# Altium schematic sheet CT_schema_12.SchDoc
size 385 x 278 mm
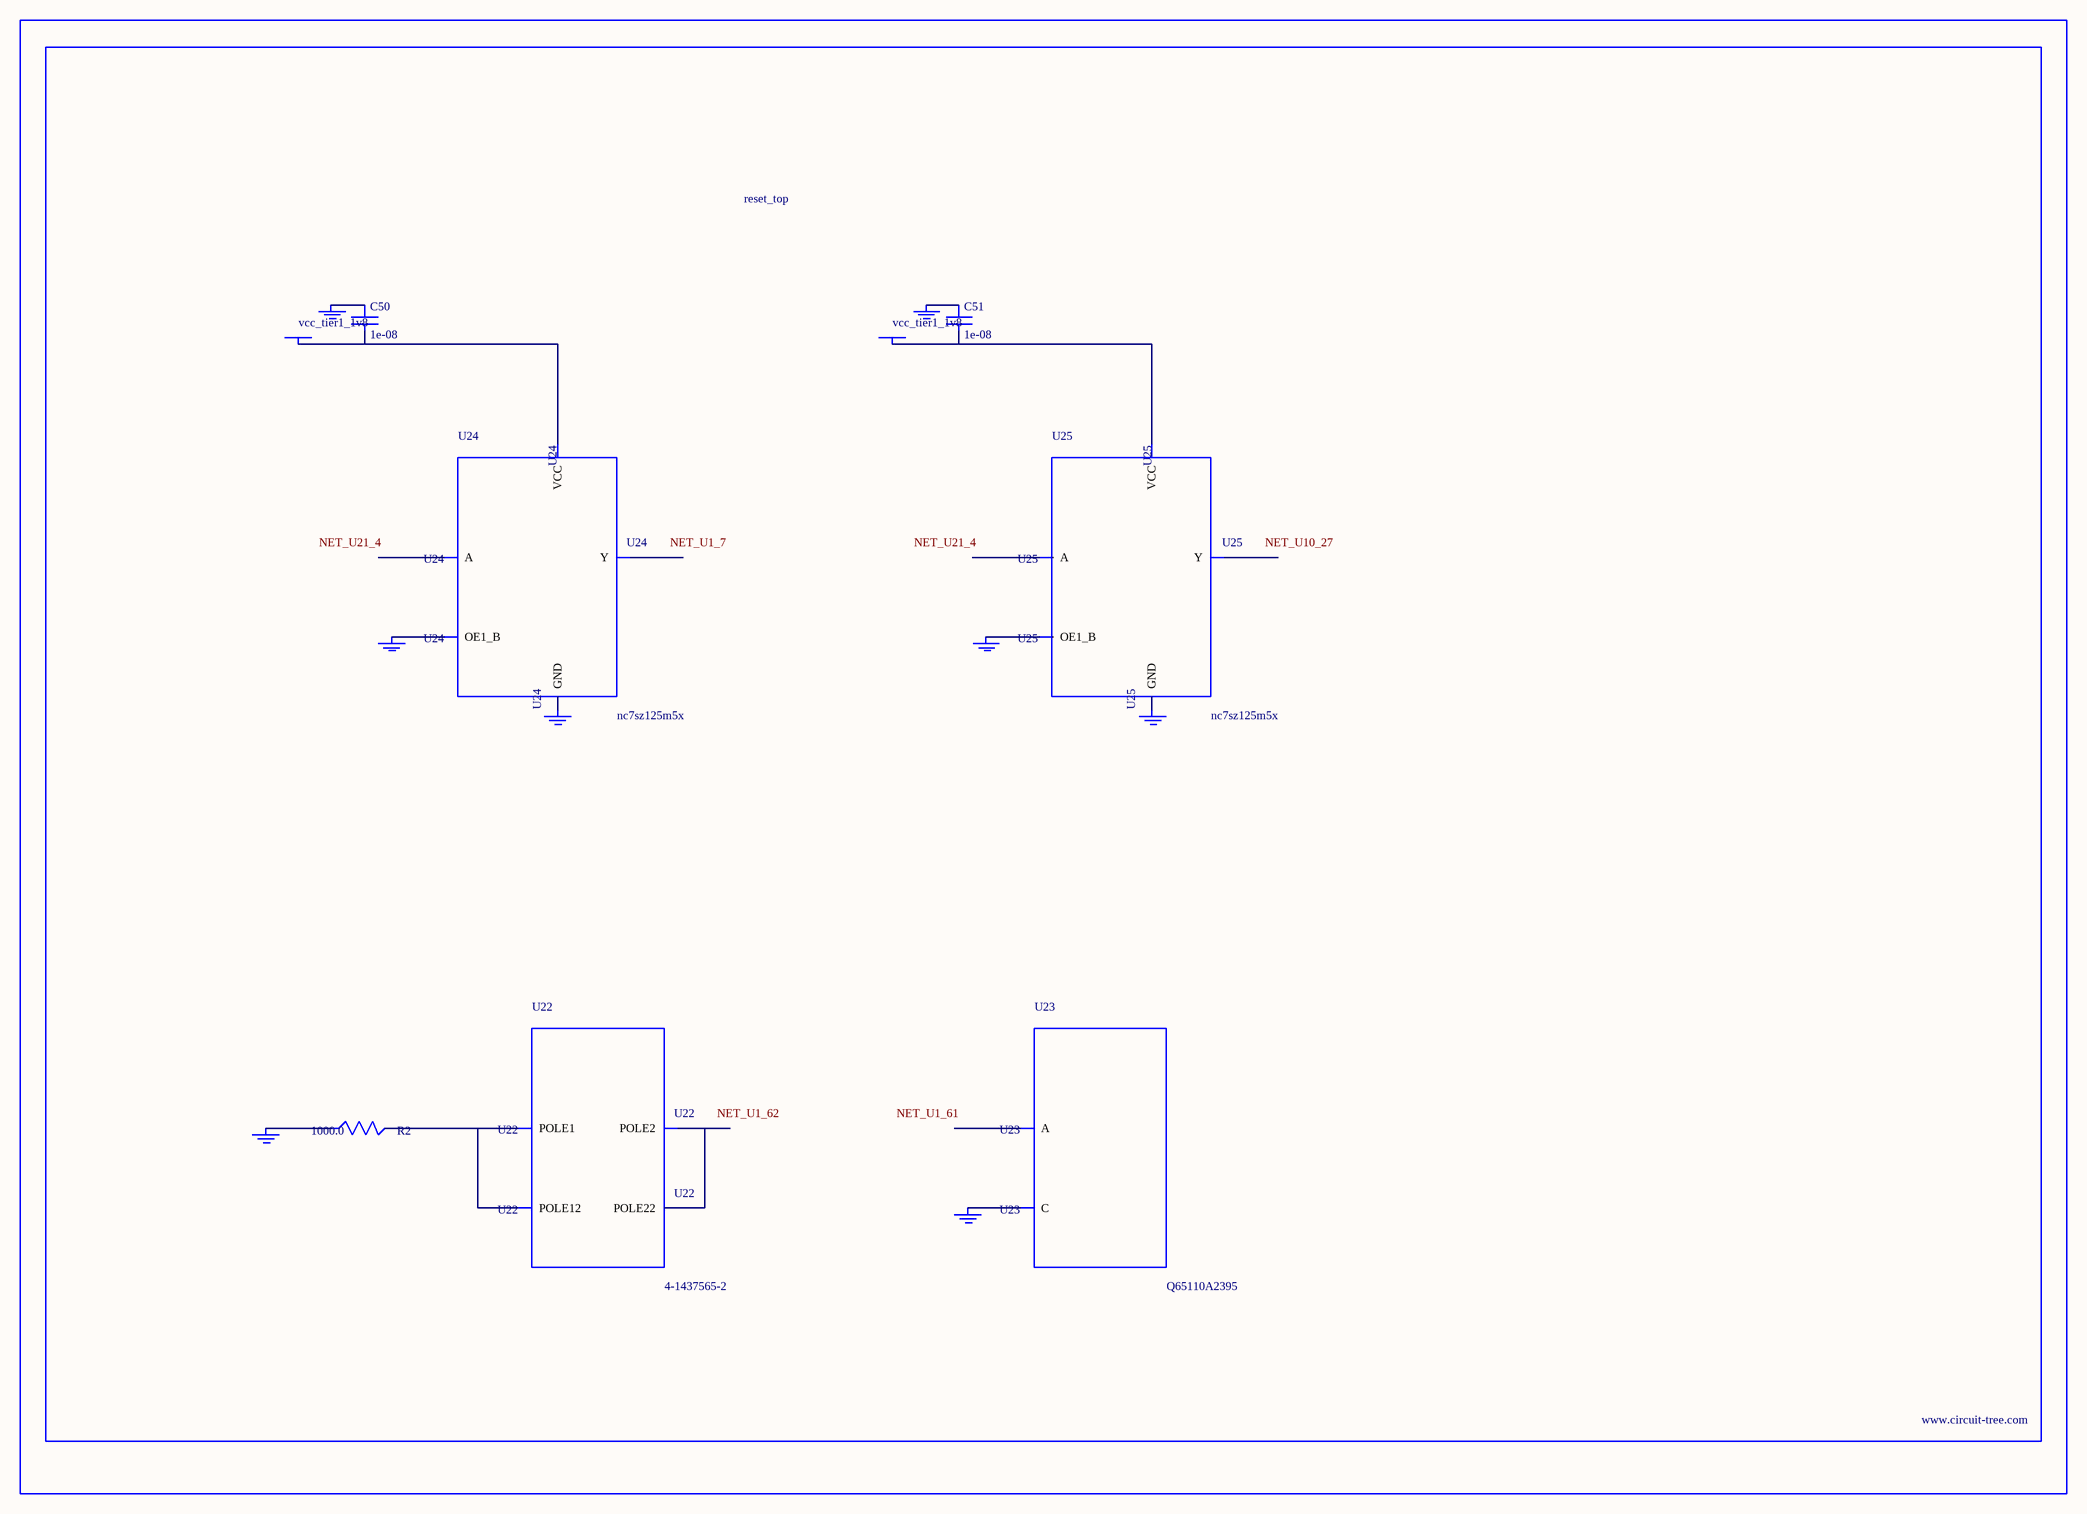
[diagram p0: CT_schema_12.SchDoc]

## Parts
BORDER11  (no value)
C50  1e-08  [C0402]
C51  1e-08  [C0402]
GND_INSTANCE_11_0  (no value)
GND_INSTANCE_11_1  (no value)
GND_INSTANCE_11_2  (no value)
GND_INSTANCE_11_3  (no value)
GND_INSTANCE_11_4  (no value)
GND_INSTANCE_11_5  (no value)
GND_INSTANCE_11_6  (no value)
GND_INSTANCE_11_7  (no value)
POWER_INSTANCE_11_0  vcc_tier1_1v8
POWER_INSTANCE_11_1  vcc_tier1_1v8
R2  1000.0  [R0603]
U22  4-1437565-2  [SW_4-1437565-2]
U23  Q65110A2395  [LGM67K-G1J2-24-Z]
U24  nc7sz125m5x  [NC7SZ125M5X]
U25  nc7sz125m5x  [NC7SZ125M5X]

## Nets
NetC50_1: C50.1 GND_INSTANCE_11_2.0(GND)
NetC50_2: C50.2 POWER_INSTANCE_11_0.0(PWR) U24.5(VCC)
NetC51_1: C51.1 GND_INSTANCE_11_5.0(GND)
NetC51_2: C51.2 POWER_INSTANCE_11_1.0(PWR) U25.5(VCC)
NetGND_INSTANCE_11_0_0: GND_INSTANCE_11_0.0(GND) R2.1
NetGND_INSTANCE_11_1_0: GND_INSTANCE_11_1.0(GND) U23.C
NetGND_INSTANCE_11_3_0: GND_INSTANCE_11_3.0(GND) U24.1(OE1_B)
NetGND_INSTANCE_11_4_0: GND_INSTANCE_11_4.0(GND) U24.3(GND)
NetGND_INSTANCE_11_6_0: GND_INSTANCE_11_6.0(GND) U25.1(OE1_B)
NetGND_INSTANCE_11_7_0: GND_INSTANCE_11_7.0(GND) U25.3(GND)
NetR2_2: R2.2 U22.1(POLE1) U22.2(POLE12)
NetU22_3: U22.3(POLE2) U22.4(POLE22)

Not connected (* = marked no-connect by the designer): U23 A; U24 2(A) 4(Y); U25 2(A) 4(Y)

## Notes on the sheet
- Labels drawn without touching a wire or pin: NET_U1_7, NET_U1_61, NET_U1_62, NET_U10_27, NET_U21_4

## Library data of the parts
BORDER11 = BORDER_PAGE11
C50 C51 = C0402C103K3RAC
GND_INSTANCE_11_0-GND_INSTANCE_11_7 = GND
POWER_INSTANCE_11_0 POWER_INSTANCE_11_1 = PWR
R2 = RC0603JR-071KL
